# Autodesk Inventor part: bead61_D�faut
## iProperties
Created: 2011-01
Part Number: bead61_D�faut
Document SubType Name: Modeling
Designer: eric
Density: 1 g/cm^3
Mass: 0.0459425 g
Surface Area: 1.08675 cm^2
Volume: 0.0459425 cm^3
Author: eric
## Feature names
1. Base1
